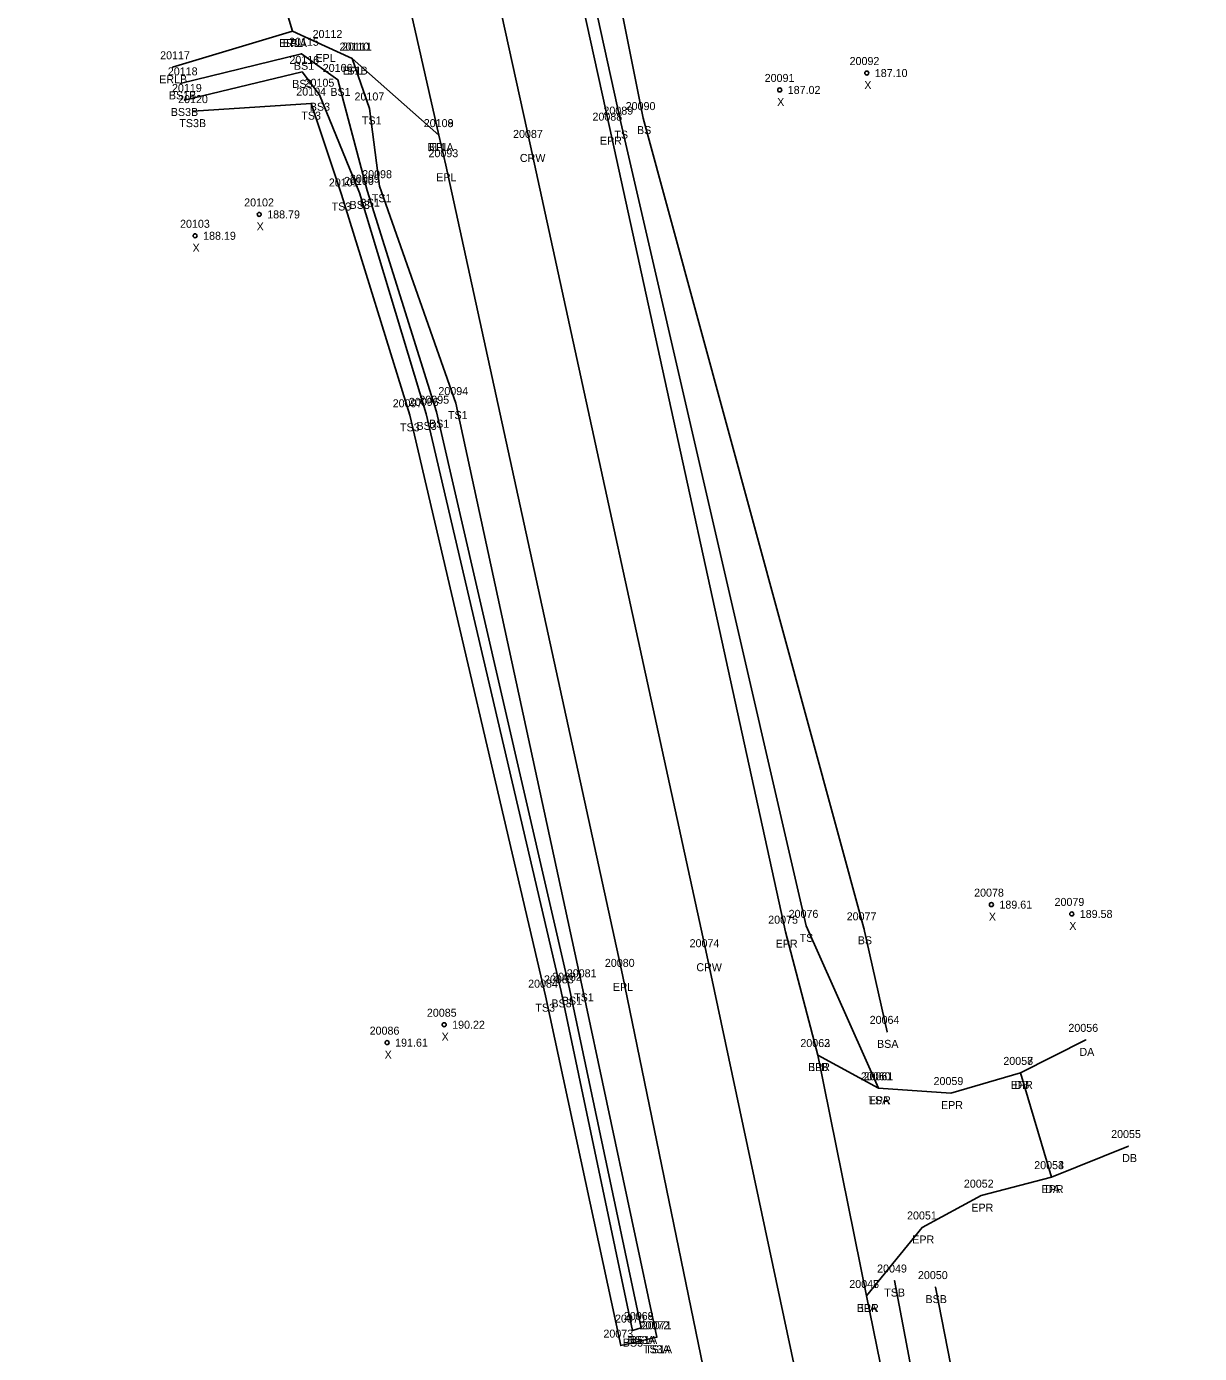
# Model space of a CAD drawing. Extents: x 2077883 to 2078272, y 787819 to 788945.
# Drawn here: x 2078090.2 to 2078236.8, y 787987.1 to 788152.9 of the extents above; entities that cross this region are included whole.
import ezdxf

# ---------------------------------------------------------------- set-up
doc = ezdxf.new("R2010")
doc.units = 0
for name, color, linetype in [('RD_DTM_BkLn1', 7, 'Continuous'), ('RD_DTM_BkLn2', 7, 'Continuous'), ('RD_EX_Driveway', 7, 'Continuous'), ('RD_EX_Driveway_txCode', 7, 'Continuous'), ('RD_EX_Road', 7, 'Continuous'), ('RD_EX_Road_txCode', 7, 'Continuous'), ('RD_Sketch8', 7, 'Continuous'), ('RD_SMD_Locator', 7, 'Continuous'), ('RD_SMD_Misc', 7, 'Continuous')]:
    doc.layers.add(name, color=color, linetype=linetype)

msp = doc.modelspace()

# ---------------------------------------------------------------- linework, layer by layer
at = {"layer": 'RD_DTM_BkLn1'}
for p, q in [((2078141.74, 788139.37), (2078134.14, 788173.23)), ((2078195.2, 787994.28), (2078189.11, 788024.39))]:
    msp.add_line(p, q, dxfattribs=at)
msp.add_lwpolyline([(2078218.47, 787830.39), (2078196.8, 787935.53), (2078175.25, 788036.87), (2078153.19, 788138.02), (2078130.35, 788242.05), (2078107.99, 788344.95), (2078104.08, 788361.32)], dxfattribs=at)
at = {"layer": 'RD_DTM_BkLn2'}
for points in [[(2078196.71, 788020.24), (2078187.64, 788040.54), (2078164.48, 788140.93), (2078157.44, 788173.03), (2078157.04, 788182.2), (2078159.94, 788189.84), (2078165.86, 788191.57)], [(2078197.77, 788027.29), (2078194.88, 788040.23), (2078167.29, 788141.5), (2078160.48, 788175.45), (2078162.44, 788179.03), (2078167.8, 788179.18)], [(2078167.05, 787990.28), (2078158.07, 788032.68), (2078141.47, 788104.8), (2078132.8, 788132.43), (2078129.15, 788146.27), (2078124.59, 788149.54), (2078109.44, 788145.84)], [(2078169, 787989.12), (2078159.62, 788033.11), (2078143.86, 788105.88), (2078134.34, 788132.99), (2078133.1, 788142.7), (2078130.94, 788148.94)], [(2078167.05, 787990.28), (2078165.97, 787989.95), (2078157.05, 788032.35), (2078140.19, 788104.53), (2078131.83, 788132.15), (2078126.86, 788144.42), (2078124.66, 788147.28), (2078109.96, 788143.76)], [(2078169, 787989.12), (2078164.48, 787988.07), (2078155.07, 788031.81), (2078138.14, 788104.35), (2078129.6, 788131.95), (2078125.82, 788143.31), (2078111.05, 788142.37)], [(2078230.74, 787832.64), (2078209.59, 787938.54), (2078198.68, 787996.21)], [(2078236.8, 787834.02), (2078214.75, 787939.4), (2078203.81, 787995.39)]]:
    msp.add_lwpolyline(points, dxfattribs=at)
at = {"layer": 'RD_EX_Driveway'}
for p, q in [((2078222.6, 788026.29), (2078214.45, 788022.16)), ((2078218.3, 788009.13), (2078227.92, 788013.02))]:
    msp.add_line(p, q, dxfattribs=at)
at = {"layer": 'RD_EX_Road'}
msp.add_line((2078123.47, 788152.38), (2078108.49, 788147.85), dxfattribs=at)
for points in [[(2078228.48, 787832.26), (2078206.7, 787937.94), (2078195.2, 787994.28), (2078202.14, 788002.84), (2078209.52, 788006.82), (2078218.3, 788009.13), (2078214.45, 788022.16), (2078205.73, 788019.64), (2078196.71, 788020.24), (2078189.11, 788024.39), (2078185.07, 788039.81), (2078163.11, 788140.18), (2078140.34, 788243.77), (2078121.8, 788330.62), (2078118.87, 788349.48), (2078108.52, 788359.43), (2078104.08, 788361.32), (2078095.01, 788364.85), (2078090.24, 788364.37)], [(2078207.78, 787828.19), (2078186.33, 787933.07), (2078181.72, 787953.57), (2078178.38, 787956.37), (2078173.08, 787956.24), (2078168.39, 787955.22), (2078162.37, 787970.77), (2078170.31, 787975.52), (2078175.69, 787980.93), (2078164.7, 788034.41), (2078142.62, 788135.61), (2078141.74, 788139.37), (2078130.94, 788148.94), (2078127.54, 788150.51), (2078123.47, 788152.38), (2078119.52, 788165.5), (2078134.14, 788173.23), (2078127.9, 788201.23), (2078119.52, 788239.75), (2078097, 788341.89), (2078090.24, 788364.37)]]:
    msp.add_lwpolyline(points, dxfattribs=at)
at = {"layer": 'RD_SMD_Locator'}
for centre, radius in [((2078123.47, 788152.38), 0.001), ((2078123.47, 788152.38), 0.001), ((2078124.59, 788149.54), 0.001), ((2078127.54, 788150.51), 0.001), ((2078108.49, 788147.85), 0.001), ((2078130.94, 788148.94), 0.001), ((2078130.94, 788148.94), 0.001), ((2078195.23, 788147.13), 0.25), ((2078109.44, 788145.84), 0.001), ((2078124.66, 788147.28), 0.001), ((2078129.15, 788146.27), 0.001), ((2078126.86, 788144.42), 0.001), ((2078184.35, 788145.02), 0.25), ((2078109.96, 788143.76), 0.001), ((2078125.82, 788143.31), 0.001), ((2078133.1, 788142.7), 0.001), ((2078111.05, 788142.37), 0.001), ((2078164.48, 788140.93), 0.001), ((2078167.29, 788141.5), 0.001), ((2078141.74, 788139.37), 0.001), ((2078141.74, 788139.37), 0.001), ((2078163.11, 788140.18), 0.001), ((2078153.19, 788138.02), 0.001), ((2078142.62, 788135.61), 0.001), ((2078134.34, 788132.99), 0.001), ((2078129.6, 788131.95), 0.001), ((2078131.83, 788132.15), 0.001), ((2078132.8, 788132.43), 0.001), ((2078119.31, 788129.46), 0.25), ((2078111.3, 788126.79), 0.25), ((2078138.14, 788104.35), 0.001), ((2078140.19, 788104.53), 0.001), ((2078141.47, 788104.8), 0.001), ((2078143.86, 788105.88), 0.001), ((2078210.8, 788043.19), 0.25), ((2078220.84, 788042.03), 0.25), ((2078185.07, 788039.81), 0.001), ((2078187.64, 788040.54), 0.001), ((2078194.88, 788040.23), 0.001), ((2078175.25, 788036.87), 0.001), ((2078159.62, 788033.11), 0.001), ((2078164.7, 788034.41), 0.001), ((2078155.07, 788031.81), 0.001), ((2078157.05, 788032.35), 0.001), ((2078158.07, 788032.68), 0.001), ((2078142.42, 788028.18), 0.25), ((2078197.77, 788027.29), 0.001), ((2078135.29, 788025.94), 0.25), ((2078222.6, 788026.29), 0.001), ((2078189.11, 788024.39), 0.001), ((2078189.11, 788024.39), 0.001), ((2078214.45, 788022.16), 0.001), ((2078214.45, 788022.16), 0.001), ((2078196.71, 788020.24), 0.001), ((2078196.71, 788020.24), 0.001), ((2078205.73, 788019.64), 0.001), ((2078227.92, 788013.02), 0.001), ((2078218.3, 788009.13), 0.001), ((2078218.3, 788009.13), 0.001), ((2078209.52, 788006.82), 0.001), ((2078202.14, 788002.84), 0.001), ((2078198.68, 787996.21), 0.001), ((2078203.81, 787995.39), 0.001), ((2078195.2, 787994.28), 0.001), ((2078195.2, 787994.28), 0.001), ((2078165.97, 787989.95), 0.001), ((2078167.05, 787990.28), 0.001), ((2078167.05, 787990.28), 0.001), ((2078169, 787989.12), 0.001), ((2078169, 787989.12), 0.001), ((2078164.48, 787988.07), 0.001)]:
    msp.add_circle(centre, radius, dxfattribs=at)

# ---------------------------------------------------------------- texts
at = {"layer": 'RD_EX_Driveway_txCode'}
for s, p in [('20056', (2078220.42, 788027.29)), ('DA', (2078221.8, 788024.29)), ('20057', (2078212.29, 788023.16)), ('DB', (2078213.67, 788020.16)), ('20055', (2078225.76, 788014.02)), ('DB', (2078227.14, 788011.02)), ('20054', (2078216.15, 788010.13)), ('DA', (2078217.51, 788007.13))]:
    msp.add_text(s, height=1, dxfattribs=at).set_placement(p)
at = {"layer": 'RD_EX_Road_txCode'}
for s, p in [('20112', (2078125.98, 788151.51)), ('ERLA', (2078121.78, 788150.38)), ('EPL', (2078122.27, 788150.38)), ('20111', (2078129.67, 788149.94)), ('20117', (2078106.93, 788148.85)), ('EPL', (2078126.33, 788148.51)), ('EPL', (2078129.74, 788146.94)), ('ERLB', (2078106.81, 788145.85)), ('20108', (2078139.87, 788140.37)), ('20088', (2078160.95, 788141.18)), ('EPR', (2078161.88, 788138.18)), ('20093', (2078140.46, 788136.61)), ('EPL', (2078140.54, 788137.37)), ('EPL', (2078141.42, 788133.61)), ('20075', (2078182.91, 788040.81)), ('EPR', (2078183.84, 788037.81)), ('20080', (2078162.5, 788035.41)), ('EPL', (2078163.5, 788032.41)), ('20062', (2078186.93, 788025.39)), ('EPR', (2078187.88, 788022.39)), ('20058', (2078212.29, 788023.16)), ('20060', (2078194.49, 788021.24)), ('20059', (2078203.57, 788020.64)), ('EPR', (2078213.22, 788020.16)), ('EPR', (2078195.48, 788018.24)), ('EPR', (2078204.5, 788017.64)), ('20053', (2078216.15, 788010.13)), ('20052', (2078207.36, 788007.82)), ('EPR', (2078217.07, 788007.13)), ('20051', (2078200.26, 788003.84)), ('EPR', (2078208.29, 788004.82)), ('EPR', (2078200.91, 788000.84)), ('20047', (2078193.04, 787995.28)), ('EPR', (2078193.97, 787992.28))]:
    msp.add_text(s, height=1, dxfattribs=at).set_placement(p)
at = {"layer": 'RD_Sketch8'}
for s, p in [('20092', (2078193.08, 788148.13)), ('187.10', (2078196.23, 788146.63)), ('20091', (2078182.47, 788146.02)), ('X', (2078194.92, 788145.13)), ('187.02', (2078185.35, 788144.52)), ('X', (2078184.03, 788143.02)), ('20102', (2078117.43, 788130.46)), ('188.79', (2078120.31, 788128.96)), ('20103', (2078109.42, 788127.79)), ('X', (2078118.99, 788127.46)), ('188.19', (2078112.3, 788126.29)), ('X', (2078110.98, 788124.79)), ('20078', (2078208.64, 788044.19)), ('189.61', (2078211.8, 788042.69)), ('20079', (2078218.69, 788043.03)), ('X', (2078210.48, 788041.19)), ('189.58', (2078221.84, 788041.53)), ('X', (2078220.53, 788040.03)), ('20085', (2078140.26, 788029.18)), ('190.22', (2078143.42, 788027.68)), ('20086', (2078133.11, 788026.94)), ('191.61', (2078136.29, 788025.44)), ('X', (2078142.1, 788026.18)), ('X', (2078134.98, 788023.94))]:
    msp.add_text(s, height=1, dxfattribs=at).set_placement(p)
at = {"layer": 'RD_SMD_Misc'}
for s, p in [('20115', (2078123.04, 788150.54)), ('20110', (2078129.35, 788149.94)), ('20116', (2078123.08, 788148.28)), ('20118', (2078107.89, 788146.84)), ('BS1', (2078123.65, 788147.54)), ('20106', (2078127.25, 788147.27)), ('TS1B', (2078129.51, 788146.94)), ('20119', (2078108.41, 788144.76)), ('BS3', (2078123.43, 788145.28)), ('20105', (2078124.98, 788145.42)), ('BS1B', (2078108.02, 788143.84)), ('20120', (2078109.18, 788143.37)), ('20104', (2078123.94, 788144.31)), ('BS1', (2078128.2, 788144.27)), ('20107', (2078131.22, 788143.7)), ('BS3B', (2078108.26, 788141.76)), ('BS3', (2078125.63, 788142.42)), ('20089', (2078162.32, 788141.93)), ('20090', (2078165.1, 788142.5)), ('TS3B', (2078109.33, 788140.37)), ('TS3', (2078124.57, 788141.31)), ('TS1', (2078132.14, 788140.7)), ('20109', (2078139.87, 788140.37)), ('20087', (2078151.03, 788139.02)), ('TS', (2078163.69, 788138.93)), ('BS', (2078166.52, 788139.5)), ('BL1A', (2078140.33, 788137.37)), ('CRW', (2078151.88, 788136.02)), ('20100', (2078129.91, 788133.15)), ('20099', (2078130.64, 788133.43)), ('20098', (2078132.18, 788133.99)), ('20101', (2078128.01, 788132.95)), ('TS3', (2078128.36, 788129.95)), ('BS3', (2078130.6, 788130.15)), ('BS1', (2078131.86, 788130.43)), ('TS1', (2078133.38, 788130.99)), ('20094', (2078141.7, 788106.88)), ('20097', (2078135.99, 788105.35)), ('20096', (2078138.01, 788105.53)), ('20095', (2078139.32, 788105.8)), ('TS1', (2078142.9, 788103.88)), ('TS3', (2078136.9, 788102.35)), ('BS3', (2078138.96, 788102.53)), ('BS1', (2078140.53, 788102.8)), ('20076', (2078185.46, 788041.54)), ('20077', (2078192.72, 788041.23)), ('20074', (2078173.09, 788037.87)), ('TS', (2078186.84, 788038.54)), ('BS', (2078194.1, 788038.23)), ('20082', (2078155.91, 788033.68)), ('20081', (2078157.74, 788034.11)), ('CRW', (2078173.93, 788034.87)), ('20084', (2078152.91, 788032.81)), ('20083', (2078154.89, 788033.35)), ('BS3', (2078155.82, 788030.35)), ('BS1', (2078157.12, 788030.68)), ('TS1', (2078158.66, 788031.11)), ('TS3', (2078153.82, 788029.81)), ('20064', (2078195.59, 788028.29)), ('20063', (2078186.93, 788025.39)), ('BSA', (2078196.51, 788025.29)), ('BLB', (2078187.88, 788022.39)), ('20061', (2078194.82, 788021.24)), ('TSA', (2078195.43, 788018.24)), ('20049', (2078196.52, 787997.21)), ('20050', (2078201.62, 787996.39)), ('20048', (2078193.04, 787995.28)), ('TSB', (2078197.41, 787994.21)), ('BLA', (2078193.96, 787992.28)), ('BSB', (2078202.56, 787993.39)), ('20070', (2078163.77, 787990.95)), ('20068', (2078164.87, 787991.28)), ('20069', (2078164.87, 787991.28)), ('20073', (2078162.32, 787989.07)), ('20072', (2078166.84, 787990.12)), ('20071', (2078167.12, 787990.12)), ('BS3', (2078164.74, 787987.95)), ('BS3A', (2078165.34, 787988.28)), ('BS1A', (2078165.62, 787988.28)), ('TS3A', (2078167.26, 787987.12)), ('TS1A', (2078167.55, 787987.12))]:
    msp.add_text(s, height=1, dxfattribs=at).set_placement(p)

doc.saveas('drawing.dxf')
